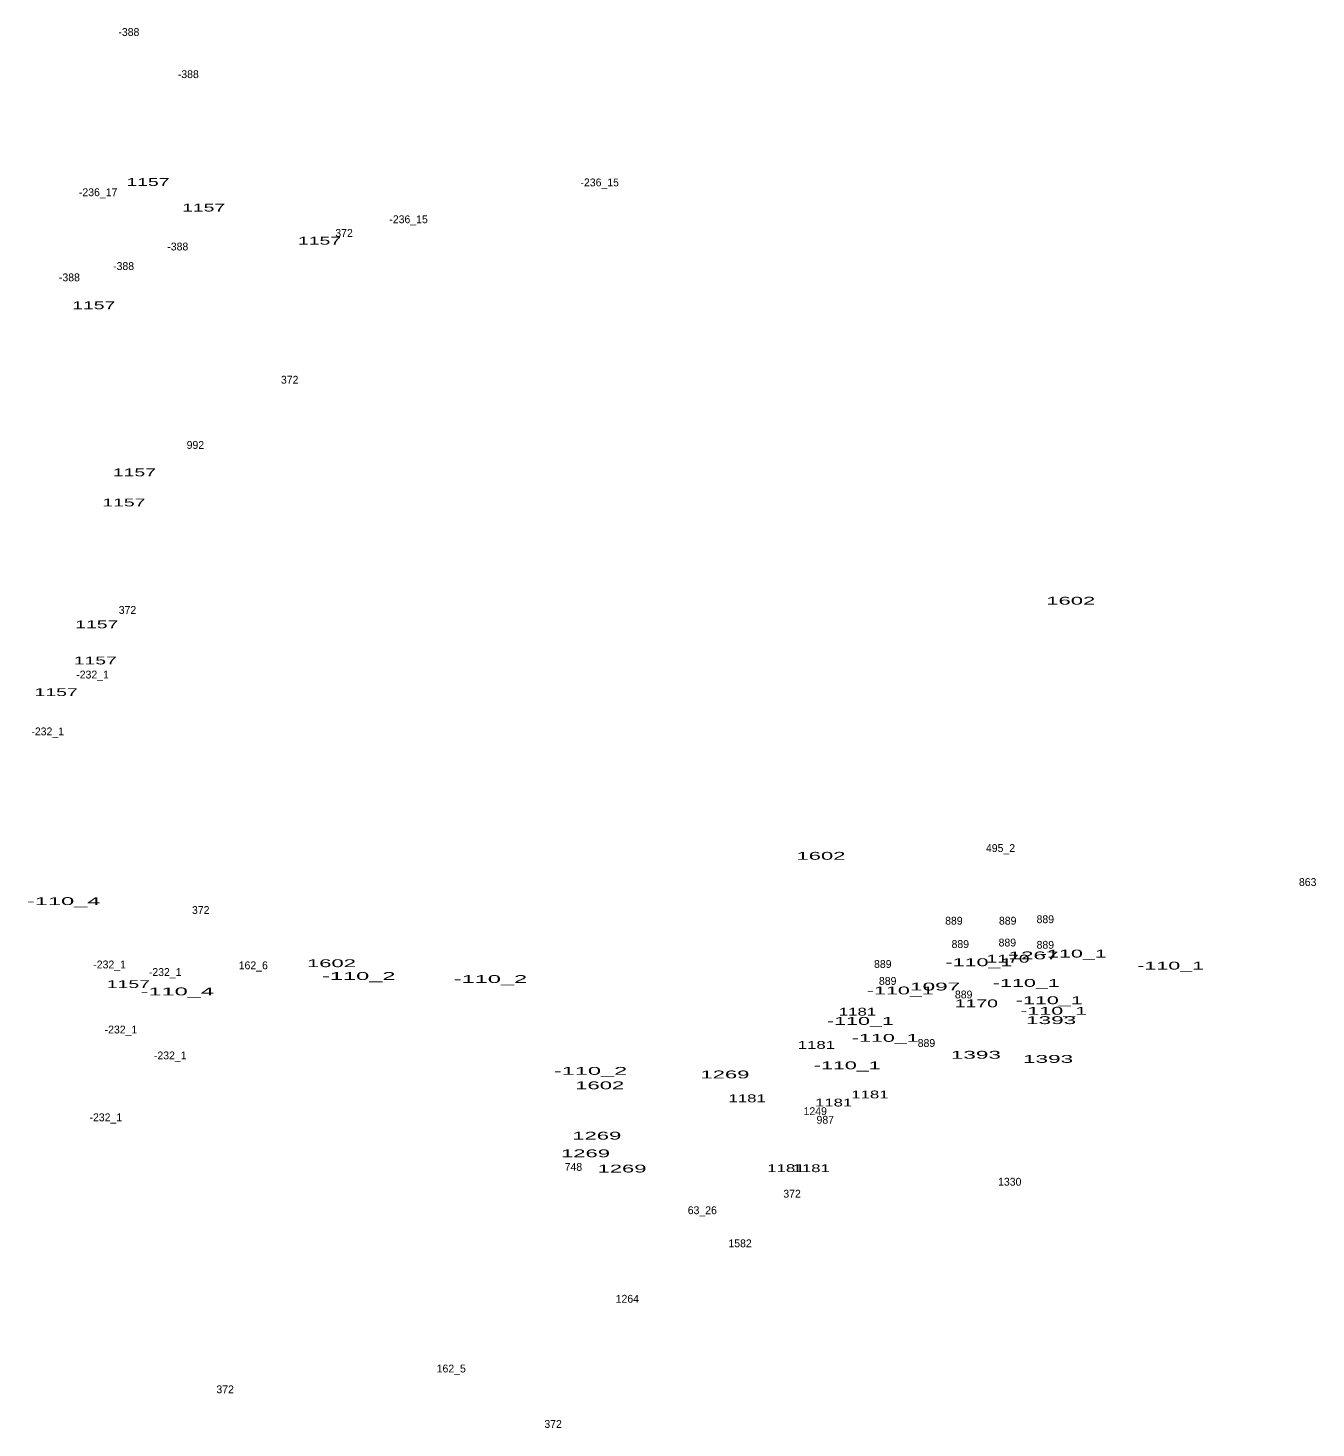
# Model space of a CAD drawing. Extents: x -660434 to -656144, y -997850 to -994016.
# Drawn here: x -657044 to -656386, y -997043 to -996328 of the extents above; entities that cross this region are included whole.
import ezdxf
from ezdxf.enums import TextEntityAlignment as Align

# ---------------------------------------------------------------- set-up
doc = ezdxf.new("R2010")
doc.units = 0
doc.header["$LTSCALE"] = 1.6
doc.layers.add('24', color=7, linetype='Continuous')

msp = doc.modelspace()

# ---------------------------------------------------------------- texts
at = {"layer": '24'}
for s, p in [('-388', (-656992.095, -996332.31)), ('-388', (-656961.755, -996353.82)), ('-236_15', (-656751.811, -996409.08)), ('-236_17', (-657007.776, -996414.1)), ('-236_15', (-656849.351, -996427.9)), ('372', (-656882.263, -996434.87)), ('-388', (-656967.125, -996441.8)), ('-388', (-656994.775, -996451.78)), ('-388', (-657022.425, -996457.55)), ('372', (-656910.013, -996509.81)), ('992', (-656958.138, -996543.1)), ('372', (-656992.803, -996627.36)), ('-232_1', (-657010.626, -996660.32)), ('-232_1', (-657033.516, -996689.34)), ('495_2', (-656547.274, -996748.89)), ('863', (-656390.503, -996766.23)), ('372', (-656955.413, -996780.52)), ('889', (-656571.063, -996785.98)), ('889', (-656543.603, -996785.98)), ('889', (-656524.403, -996785.22)), ('889', (-656567.793, -996797.89)), ('889', (-656543.793, -996797.12)), ('889', (-656524.403, -996798.28)), ('-232_1', (-657001.926, -996808.31)), ('-232_1', (-656973.566, -996812.18)), ('162_6', (-656928.6, -996808.75)), ('889', (-656607.353, -996808.07)), ('889', (-656604.853, -996816.72)), ('889', (-656566.073, -996823.63)), ('-232_1', (-656996.126, -996841.52)), ('889', (-656585.073, -996848.41)), ('-232_1', (-656970.986, -996854.74)), ('1249', (-656641.83, -996883.19)), ('-232_1', (-657003.856, -996886.34)), ('987', (-656636.698, -996887.6)), ('748', (-656765.227, -996911.65)), ('1330', (-656542.564, -996919.22)), ('372', (-656653.643, -996925.33)), ('63_26', (-656699.456, -996933.78)), ('1582', (-656680.18, -996950.67)), ('1264', (-656737.72, -996978.98)), ('162_5', (-656827.574, -997014.58)), ('372', (-656942.953, -997025.19)), ('372', (-656775.593, -997042.88))]:
    msp.add_text(s, height=4, dxfattribs=at).set_placement(p, align=Align.CENTER)
for s, width, p in [('1157', 1.85, (-656982.349, -996408.87)), ('1157', 1.85, (-656953.929, -996421.93)), ('1157', 1.85, (-656894.789, -996438.83)), ('1157', 1.85, (-657009.999, -996471.82)), ('1157', 1.85, (-656989.259, -996557.1)), ('1157', 1.85, (-656994.639, -996572.47)), ('1602', 2.1, (-656511.409, -996622.62)), ('1157', 1.85, (-657008.459, -996634.7)), ('1157', 1.85, (-657009.229, -996653.14)), ('1157', 1.85, (-657029.199, -996669.28)), ('1602', 2.1, (-656638.899, -996752.85)), ('-110_4', 2.25, (-657025.359, -996775.98)), ('1170', 1.85, (-656543.465, -996805.36)), ('1267', 2.15, (-656530.447, -996803.69)), ('-110_1', 2.05, (-656510.1, -996802.76)), ('1602', 2.1, (-656888.699, -996807.67)), ('-110_1', 2.05, (-656558.29, -996807.18)), ('-110_1', 2.05, (-656460.43, -996808.91)), ('1157', 1.85, (-656992.329, -996818.33)), ('-110_2', 2.25, (-656874.774, -996814.21)), ('-110_2', 2.25, (-656807.574, -996815.75)), ('1097', 2.15, (-656580.643, -996819.58)), ('-110_1', 2.05, (-656534.1, -996817.74)), ('-110_4', 2.25, (-656967.379, -996822.08)), ('-110_1', 2.05, (-656598.42, -996821.59)), ('-110_1', 2.05, (-656522.39, -996826.58)), ('1181', 1.6, (-656620.25, -996832.42)), ('1170', 1.85, (-656559.595, -996828.16)), ('-110_1', 2.05, (-656520.14, -996831.96)), ('-110_1', 2.05, (-656618.77, -996837.14)), ('1393', 2.15, (-656521.453, -996836.74)), ('-110_1', 2.05, (-656606.1, -996845.79)), ('1181', 1.6, (-656641.23, -996849.38)), ('1393', 2.15, (-656559.853, -996854.41)), ('-110_2', 2.25, (-656756.494, -996862.62)), ('-110_1', 2.05, (-656625.49, -996859.81)), ('1393', 2.15, (-656522.993, -996856.53)), ('1602', 2.1, (-656751.799, -996870.01)), ('1269', 2.1, (-656687.907, -996864.45)), ('1181', 1.6, (-656676.56, -996876.65)), ('1181', 1.6, (-656613.92, -996874.67)), ('1181', 1.6, (-656632.44, -996878.8)), ('1269', 2.1, (-656753.297, -996895.71)), ('1269', 2.1, (-656759.057, -996904.73)), ('1269', 2.1, (-656740.427, -996912.51)), ('1181', 1.6, (-656656.78, -996912.28)), ('1181', 1.6, (-656643.87, -996912.32))]:
    msp.add_text(s, height=4, dxfattribs=dict(at, width=width)).set_placement(p, align=Align.CENTER)

doc.saveas('drawing.dxf')
